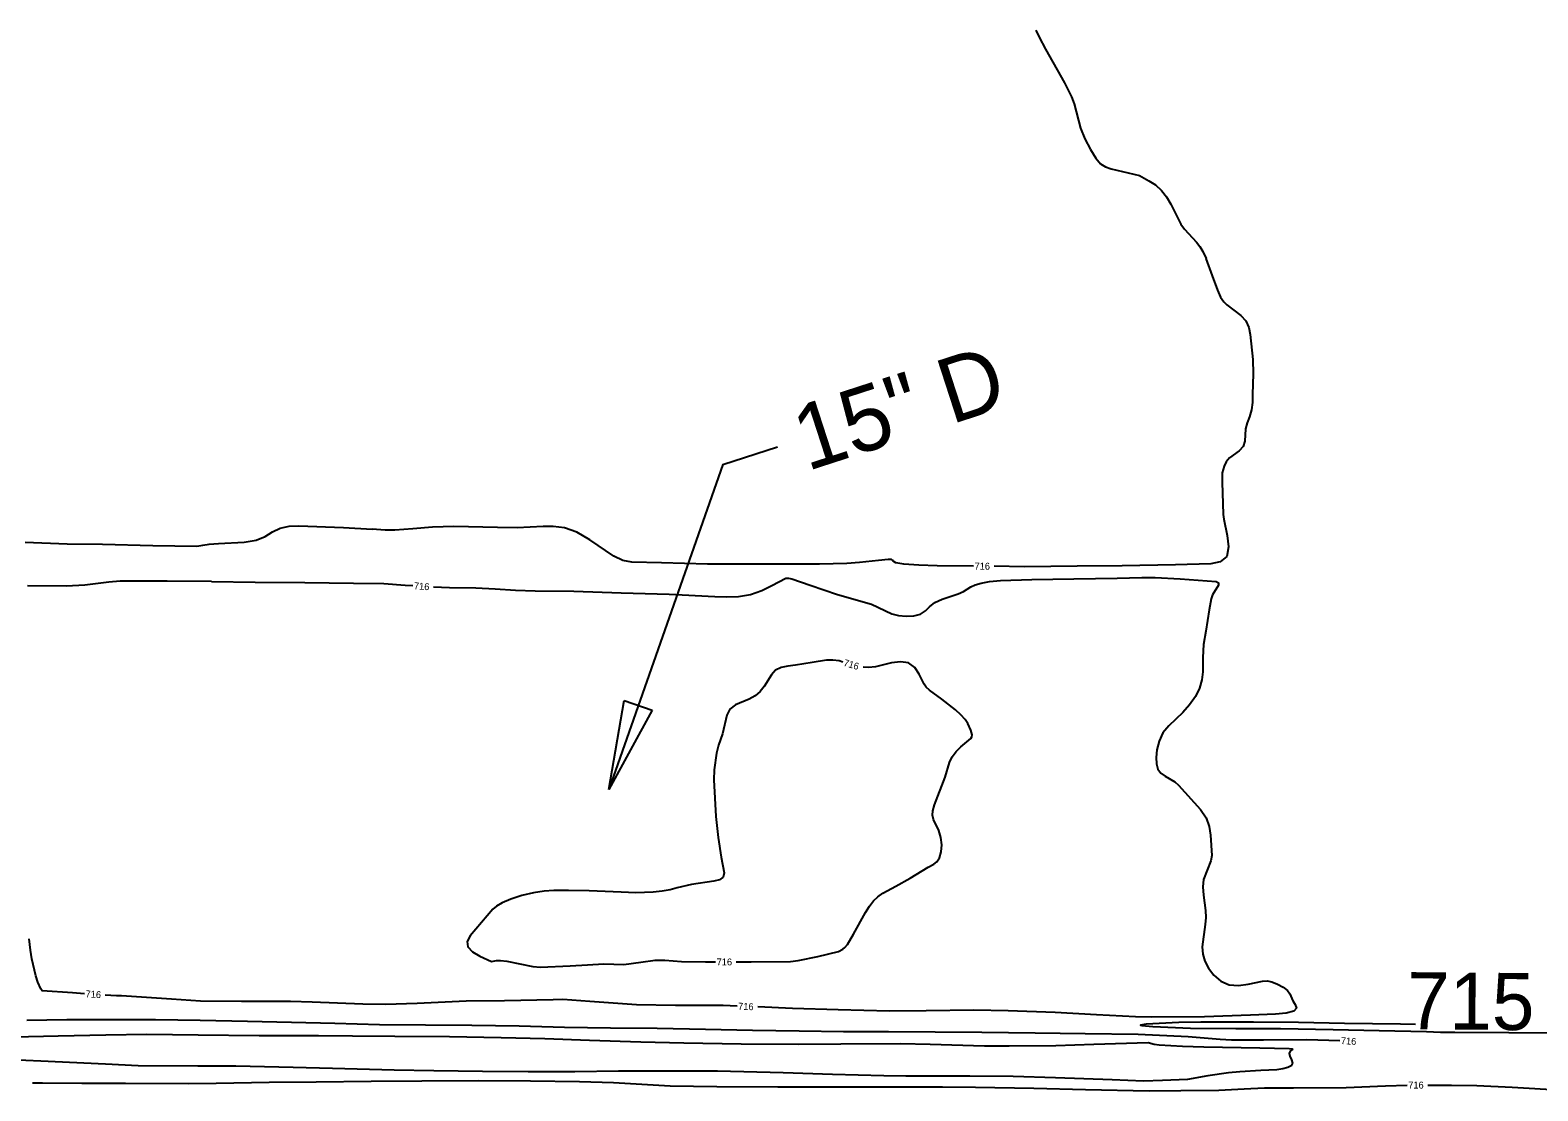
# Model space of a CAD drawing. Extents: x -468563856 to 36492962, y -306094093 to 11899197.
# Drawn here: x 1820533 to 1821405, y 530967 to 531580 of the extents above; entities that cross this region are included whole.
import ezdxf

# ---------------------------------------------------------------- set-up
doc = ezdxf.new("R2010")
doc.units = 0
for name, color, linetype in [('DT_X_Contour_Minor', 7, 'Continuous'), ('Level 19', 7, 'Continuous'), ('Level 40', 7, 'Continuous')]:
    doc.layers.add(name, color=color, linetype=linetype)

msp = doc.modelspace()

# ---------------------------------------------------------------- linework, layer by layer
at = {"layer": 'DT_X_Contour_Minor'}
for points in [[(1821114.48, 531580.1), (1821116.48, 531576.07), (1821120.12, 531569.12), (1821131.16, 531549.72), (1821135.12, 531541.66), (1821136.65, 531537.51), (1821140.41, 531523.39), (1821142.96, 531517.26), (1821146.08, 531511.13), (1821149.22, 531506.07), (1821152.02, 531502.86), (1821154.81, 531501.08), (1821158.09, 531500.02), (1821174.51, 531496.08), (1821179.96, 531493.1), (1821183.66, 531490.61), (1821187.24, 531487.45), (1821190.16, 531483.68), (1821192.52, 531479.57), (1821198.36, 531468.06), (1821200.44, 531464.98), (1821205.14, 531459.97), (1821207.4, 531457.64), (1821209.37, 531455.12), (1821211.16, 531452.09), (1821212.95, 531448.13)], [(1821212.94, 531448.13), (1821216.58, 531438.06), (1821219.53, 531429.82), (1821221.37, 531425.72), (1821223.16, 531423.01), (1821224.91, 531421.25), (1821233.08, 531415.23), (1821235.91, 531412.05), (1821237.62, 531408.33), (1821238.49, 531404.12), (1821239.94, 531389.83), (1821240.2, 531381.47), (1821239.91, 531369.6), (1821239.8, 531364.98), (1821239.26, 531360.57), (1821238.12, 531356.68), (1821236.77, 531353.13), (1821235.79, 531349.65), (1821235.3, 531342.53), (1821234.37, 531339.46), (1821232.17, 531337.04), (1821226.49, 531332.93), (1821224.54, 531330.56), (1821223.35, 531328.11), (1821222.34, 531324.18), (1821222.25, 531318.89), (1821222.84, 531300.07), (1821223.16, 531297.43), (1821225.22, 531287.99), (1821225.96, 531281.43), (1821224.9, 531275.92), (1821221.21, 531272.84), (1821215.82, 531271.67), (1821195.31, 531271.05), (1821164.57, 531270.55), (1821138.38, 531270.3), (1821108.08, 531269.97), (1821090.5, 531270.21)], [(1820530.32, 531284.19), (1820554.56, 531283.23), (1820575.05, 531282.98), (1820604.06, 531282.28), (1820629.47, 531281.76), (1820633.02, 531282.51), (1820636.73, 531283.06), (1820642.12, 531283.48), (1820656.91, 531284.12), (1820663.86, 531285.29), (1820669.11, 531287.5), (1820673.35, 531290.12), (1820677.66, 531292.29), (1820682.84, 531293.35), (1820688.54, 531293.56), (1820714.27, 531292.7), (1820730.84, 531291.63)], [(1821078.5, 531270.35), (1821057.63, 531270.57), (1821046.88, 531270.87), (1821038.34, 531271.42), (1821033.73, 531272.24), (1821032.05, 531273.13), (1821031.62, 531273.84), (1821031.06, 531274.17), (1821029.27, 531274.14), (1821023.61, 531273.59), (1821012.72, 531272.31), (1821005.3, 531271.74), (1820989.54, 531271.43), (1820959.72, 531271.47), (1820924.77, 531271.43), (1820898.19, 531272.17), (1820881.01, 531272.68), (1820875.75, 531273.61), (1820870.59, 531276.04), (1820856.83, 531285.58), (1820849.28, 531289.97), (1820842.16, 531292.41), (1820835.64, 531293.26), (1820829.81, 531293.23), (1820814.81, 531292.45), (1820803.42, 531292.58), (1820778.15, 531293.23), (1820765.74, 531292.92), (1820754.5, 531291.94), (1820743.97, 531291.1), (1820738.45, 531291.18), (1820730.84, 531291.63)], [(1820638.06, 531261.5), (1820612.33, 531261.55), (1820593.86, 531261.7), (1820585.15, 531261.53), (1820578.65, 531261.06), (1820564.8, 531259.27), (1820554.3, 531258.8), (1820531.6, 531258.86)], [(1820638.06, 531261.5), (1820663.23, 531261.02), (1820692, 531260.86), (1820720.16, 531260.5), (1820737.68, 531260.19), (1820749.91, 531259.36), (1820754.44, 531259.03)], [(1820766.41, 531258.26), (1820775.71, 531257.98), (1820790.89, 531257.75), (1820801.94, 531257.11), (1820813.7, 531256.32), (1820825.15, 531256.05), (1820847.4, 531255.88), (1820874.94, 531254.8), (1820902.56, 531254.1), (1820929.1, 531252.7), (1820935.84, 531252.48), (1820942.72, 531252.71), (1820949.58, 531253.88), (1820956.2, 531256.23), (1820962.02, 531259.08), (1820970.03, 531263.4), (1820971.5, 531263.37), (1820973.49, 531262.89), (1820984.06, 531259.33), (1820999.95, 531253.98), (1821019.48, 531248.35), (1821031.29, 531242.73), (1821035.1, 531241.81), (1821039.54, 531241.37), (1821044.07, 531241.57), (1821047.95, 531242.59), (1821050.74, 531244.48), (1821053.15, 531246.86), (1821056.17, 531249.24), (1821060.45, 531251.22), (1821069.6, 531254.31), (1821072.68, 531255.7), (1821076.95, 531258.32), (1821079.47, 531259.5), (1821082.93, 531260.53), (1821087.77, 531261.35), (1821094.14, 531261.92), (1821112.33, 531262.61), (1821136.59, 531262.9), (1821161.6, 531263.29), (1821175.83, 531263.72), (1821183.59, 531263.73), (1821198.04, 531263), (1821218.73, 531261.39), (1821220.17, 531260.62), (1821220.16, 531259.29), (1821216.77, 531253.67), (1821215.96, 531251.45), (1821214.72, 531245.06), (1821212.76, 531232.68), (1821211.51, 531225.04), (1821211.1, 531217.47), (1821211.02, 531209.13), (1821210.54, 531204.56), (1821209.24, 531199.8), (1821206.83, 531194.94), (1821203.5, 531190.18), (1821199.57, 531185.77), (1821191.38, 531178), (1821188.08, 531173.86), (1821185.85, 531169.14), (1821184.59, 531164.22), (1821184.11, 531159.67), (1821184.26, 531155.95), (1821185.1, 531153.01), (1821186.76, 531150.7), (1821189.26, 531148.84), (1821194.86, 531145.54), (1821197.05, 531143.63), (1821209.71, 531129.73), (1821213.01, 531124.82), (1821214.85, 531119.78), (1821215.6, 531114.89), (1821216.28, 531103.14), (1821215.76, 531099.92), (1821211.51, 531089.26), (1821211.18, 531084.86), (1821211.53, 531080.19), (1821212.61, 531071.28), (1821212.79, 531067.18), (1821212.54, 531063.08), (1821210.65, 531050.23), (1821211.02, 531046.07), (1821212.27, 531041.97), (1821214.41, 531037.87), (1821217.47, 531033.81), (1821221.43, 531030.36), (1821226.24, 531028.23), (1821231.75, 531027.87), (1821237.29, 531028.67), (1821245.62, 531030.49), (1821248.37, 531030.58), (1821251.09, 531030), (1821254.29, 531028.75), (1821257.52, 531027.02), (1821260.06, 531025.08), (1821261.47, 531023.13), (1821263.13, 531019.09), (1821264.51, 531016.89), (1821265.24, 531014.8), (1821263.81, 531013.07)], [(1821003.03, 531214.87), (1821000.87, 531215.51), (1820997.15, 531216.02), (1820993.57, 531215.93), (1820985.23, 531214.62), (1820975.63, 531213.01), (1820971.22, 531212.45), (1820967.35, 531211.65), (1820964.16, 531210.11), (1820961.67, 531207.48), (1820957.56, 531200.77), (1820955.2, 531197.79), (1820952.36, 531195.31), (1820948.91, 531193.34), (1820940.91, 531190.07), (1820937.73, 531187.69), (1820935.89, 531184.23), (1820933.39, 531173.38), (1820931.09, 531166.89), (1820930.03, 531162.17), (1820928.64, 531152.57), (1820928.48, 531146.79), (1820929.64, 531125.54), (1820930.97, 531113.5), (1820932.62, 531102.14), (1820934.39, 531092.98), (1820933.8, 531090.48), (1820931.76, 531088.98), (1820928.51, 531088.2), (1820915.59, 531086.33), (1820907.23, 531084.35), (1820903.16, 531083.29), (1820898.63, 531082.41), (1820893.4, 531081.83), (1820883.29, 531081.45), (1820874.85, 531081.92), (1820856.4, 531082.56), (1820844.36, 531082.86), (1820835.93, 531082.81), (1820830.4, 531082.47), (1820824.15, 531081.55), (1820817.46, 531079.87), (1820811.12, 531077.76), (1820806.02, 531075.63), (1820802.77, 531073.79), (1820800.7, 531071.97), (1820787.62, 531056.59), (1820785.88, 531053.34), (1820786.18, 531050.26), (1820789.01, 531047.4), (1820793.16, 531044.96), (1820799.99, 531041.82), (1820802.71, 531042.27), (1820805.19, 531042.35), (1820808.76, 531041.98), (1820823.8, 531038.83), (1820828.29, 531038.5), (1820845.41, 531039.2), (1820855.39, 531039.82), (1820864.84, 531040.39), (1820876.44, 531040.04), (1820886.31, 531041.34), (1820894.6, 531042.47), (1820900.19, 531042.46), (1820909.82, 531041.71), (1820923.66, 531041.52), (1820929.41, 531041.52)], [(1820941.41, 531041.52), (1820950, 531041.53), (1820972.76, 531041.76), (1820977.16, 531042.34), (1820988.47, 531044.62), (1821000.56, 531047.64), (1821003.08, 531048.85), (1821004.22, 531049.83), (1821005.62, 531051.53), (1821009.22, 531057.59), (1821016.01, 531070.01), (1821018.37, 531073.75), (1821020.67, 531076.78), (1821023.15, 531079.22), (1821026.07, 531081.33), (1821033.59, 531085.35), (1821041.83, 531089.89), (1821052.25, 531096.29), (1821055.53, 531098), (1821057.34, 531099.46), (1821058.89, 531101.78), (1821059.9, 531105.14), (1821060.21, 531109.19), (1821059.72, 531113.43), (1821058.42, 531117.42), (1821055.4, 531123.92), (1821054.74, 531126.32), (1821054.95, 531128.83), (1821056.03, 531132.27), (1821062.15, 531148.33), (1821064.62, 531156.77), (1821066.15, 531160.1), (1821068.5, 531163.17), (1821071.26, 531165.89), (1821077.01, 531170.76), (1821077.63, 531171.73), (1821077.72, 531172.77), (1821076.91, 531175.45), (1821075.28, 531179.28), (1821073.69, 531181.65), (1821071.29, 531184.31), (1821068.14, 531187.2), (1821060.22, 531193.4), (1821053.07, 531198.71), (1821051.18, 531200.42), (1821050.04, 531202.06), (1821047.22, 531207.92), (1821044.64, 531211.65), (1821041.03, 531214.33), (1821036.39, 531215.07), (1821031.22, 531214.38), (1821021.81, 531212.15), (1821017.81, 531211.68), (1821014.66, 531211.87)], [(1820564.62, 531023.17), (1820557.65, 531023.62), (1820540.13, 531024.74), (1820539.44, 531025.93), (1820537.73, 531029.87), (1820536.55, 531033.42), (1820534.13, 531043.37), (1820533.31, 531048.28), (1820532.58, 531054.96)], [(1820941.84, 531015.99), (1820933.8, 531016.27), (1820906.26, 531016.44), (1820883.74, 531016.81), (1820856.72, 531018.73), (1820841.11, 531019.79), (1820835.61, 531019.58), (1820807.42, 531019.13), (1820785.3, 531018.81), (1820756.95, 531017.56), (1820738.69, 531016.86), (1820725.61, 531017.04), (1820696.22, 531018.27), (1820683.65, 531018.58), (1820655.37, 531018.58), (1820631.64, 531018.84), (1820614.84, 531019.94), (1820586.04, 531021.86), (1820583.17, 531021.99), (1820576.6, 531022.41)], [(1820531.19, 531007.79), (1820554.4, 531008.3), (1820579.68, 531008.27), (1820605.58, 531008.18), (1820631.47, 531007.8), (1820658.91, 531007.2), (1820684.19, 531006.78), (1820709.39, 531006.23), (1820735.25, 531005.45), (1820761.84, 531005.17), (1820788.46, 531005.06), (1820815.81, 531004.52), (1820842.09, 531003.77), (1820868.65, 531003.41), (1820895.65, 531003.22), (1820923.69, 531002.66), (1820950.76, 531002.01), (1820977.67, 531001.65), (1821003.39, 531001.41), (1821029.47, 531001.32), (1821056.41, 531001.17), (1821083.4, 531000.86), (1821114.18, 531000.61), (1821143.12, 531000.22), (1821173.68, 530999.79), (1821202.67, 530998.48), (1821221.08, 530996.95), (1821227.6, 530996.5), (1821246.11, 530996.56), (1821271.28, 530996.74), (1821290.28, 530996.07)], [(1821263.81, 531013.07), (1821259.28, 531011.94), (1821253.03, 531011.29), (1821238.74, 531010.69), (1821212, 531009.83), (1821181.38, 531009.61), (1821172.23, 531009.79), (1821149.65, 531011.04), (1821125.81, 531012.33), (1821098.55, 531013.22), (1821078.8, 531013.72), (1821051.08, 531013.36), (1821030.06, 531013.16), (1821000.37, 531013.84), (1820973.95, 531014.62), (1820953.83, 531015.49)], [(1820523.7, 530998.33), (1820549.42, 530998.81), (1820577.03, 530999.35), (1820600.61, 530999.73), (1820630.38, 530999.35), (1820665.58, 530999.06), (1820699.97, 530999.02), (1820719.56, 530998.91), (1820744, 530998.72), (1820775.63, 530998.39), (1820805.54, 530997.93), (1820830.73, 530997.33), (1820856.55, 530996.33), (1820886.21, 530995.28), (1820911, 530994.7), (1820944.32, 530994.18), (1820977.2, 530994.09), (1821001.78, 530994.22), (1821036.31, 530994.47), (1821053.54, 530994.02), (1821084.81, 530993.11), (1821099.09, 530992.98), (1821126.21, 530993.29), (1821148.12, 530993.95), (1821179.43, 530994.97), (1821182.91, 530993.98), (1821185.9, 530993.59), (1821199.32, 530992.87), (1821211.66, 530992.45), (1821244.14, 530991.91), (1821260.95, 530991.53), (1821262.85, 530991.27), (1821262.86, 530990.83), (1821261.86, 530990.08), (1821261.11, 530988.84), (1821261.5, 530987.04), (1821262.43, 530984.98), (1821262.89, 530983.04), (1821262.11, 530981.53), (1821260.16, 530980.45), (1821257.32, 530979.71), (1821253.82, 530979.24), (1821244.68, 530978.7), (1821232.59, 530978.09), (1821226.04, 530977.52), (1821213.99, 530975.76), (1821202.21, 530973.57), (1821187.85, 530972.91), (1821176.73, 530972.68), (1821158.63, 530973.35), (1821125.86, 530974.55), (1821101.5, 530975.29), (1821076.43, 530975.59), (1821039.45, 530975.53), (1821026.61, 530975.72), (1820997.04, 530976.53), (1820968.55, 530977.34), (1820930.54, 530978.31), (1820910.78, 530978.41), (1820873.33, 530978.44), (1820848.1, 530978.08), (1820821.13, 530978.05), (1820794.63, 530978.26), (1820766.65, 530978.55), (1820743.7, 530979.05), (1820707.93, 530980), (1820685.25, 530980.45), (1820652.09, 530981.19), (1820630.19, 530981.27), (1820595.61, 530981.49), (1820576.84, 530982.39), (1820539.43, 530984.19), (1820513.21, 530985.33)], [(1821334.01, 531005.37), (1821325.41, 531005.48), (1821293.09, 531005.99), (1821266.32, 531006.47), (1821240.43, 531006.7), (1821209.88, 531006.69), (1821197.28, 531006.53), (1821178.37, 531005.59), (1821175.02, 531005.03), (1821175.88, 531004.74), (1821182.3, 531004.16), (1821204.07, 531003.16), (1821230.1, 531003.09), (1821255.95, 531002.99), (1821286.48, 531002.44), (1821313.04, 531001.97), (1821340.43, 531001.35), (1821348.41, 531000.9), (1821356.79, 531000.97), (1821388.03, 531000.73), (1821414.14, 531000.46)], [(1820534.53, 530971.68), (1820540.37, 530971.66), (1820563.15, 530971.55), (1820588.26, 530971.46), (1820624.51, 530971.31), (1820640.75, 530971.42), (1820671.28, 530971.99), (1820698.54, 530972.31), (1820730.34, 530972.63), (1820759.54, 530972.9), (1820792.19, 530972.97), (1820822.35, 530972.73), (1820850.85, 530972.39), (1820870.34, 530971.81), (1820903.28, 530969.97), (1820930.23, 530969.62), (1820965.33, 530969.25), (1820994.7, 530969.35), (1821026.47, 530969.38), (1821060.57, 530969.39), (1821079.61, 530969.2), (1821113.51, 530968.54), (1821143.23, 530967.86), (1821180.02, 530967.02), (1821198.33, 530967.15), (1821220.4, 530967.46), (1821234.95, 530968.09), (1821246.74, 530968.72), (1821263.59, 530968.75), (1821293.94, 530968.9), (1821316.73, 530969.84), (1821329.2, 530970.22)], [(1821341.2, 530970.35), (1821354.93, 530970.33), (1821369.57, 530970.05), (1821389.97, 530969.09), (1821419.18, 530967.44)]]:
    msp.add_lwpolyline(points, dxfattribs=at)
at = {"layer": 'Level 40'}
for p, q in [((1820933.69, 531329.07), (1820965.3, 531339.33)), ((1820933.69, 531329.07), (1820867.65, 531141.16)), ((1820867.65, 531141.16), (1820876.66, 531192.66)), ((1820876.66, 531192.66), (1820892.87, 531186.96)), ((1820892.87, 531186.96), (1820867.65, 531141.16))]:
    msp.add_line(p, q, dxfattribs=at)

# ---------------------------------------------------------------- texts
at = {"layer": 'Level 19'}
for s, height, rotation, p in [('716', 4, 359.21589, (1821079.12, 531268.36)), ('716', 4, 355.85263, (1820754.94, 531256.99)), ('716', 4, 343.47674, (1821003.08, 531212.77)), ('716', 4, 0.01146, (1820930.05, 531039.52)), ('715', 33, 359.54248, (1821329.05, 531002.66)), ('716', 4, 356.34537, (1820565.14, 531021.14)), ('716', 4, 357.53139, (1820942.4, 531013.98)), ('716', 4, 356.36256, (1821290.8, 530994.09)), ('716', 4, 359.93209, (1821329.85, 530968.36))]:
    msp.add_text(s, height=height, rotation=rotation, dxfattribs=at).set_placement(p)
at = {"layer": 'Level 40'}
msp.add_text('15" D', height=37.5, rotation=17.9864, dxfattribs=at).set_placement((1820982.29, 531325.07))

doc.saveas('drawing.dxf')
